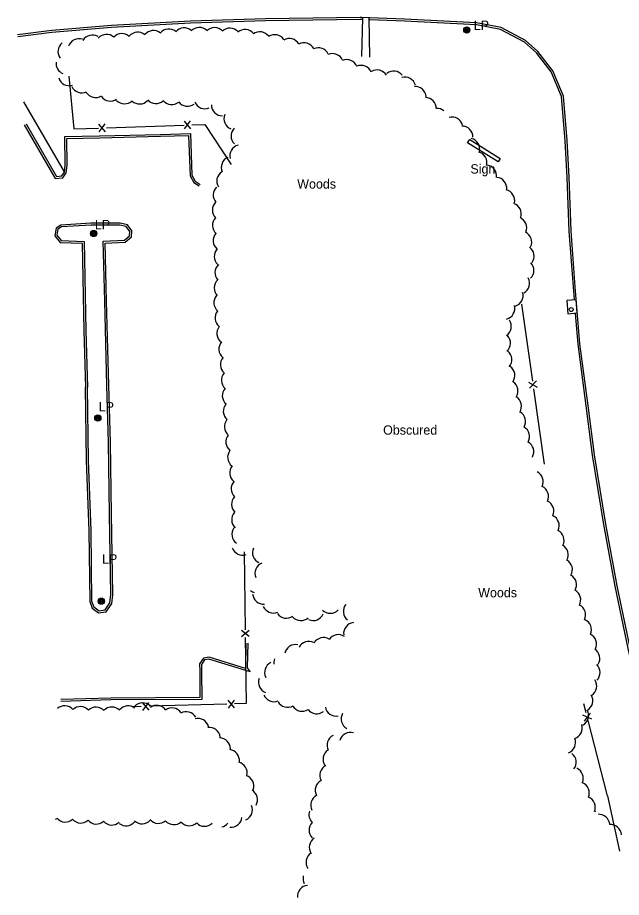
# Model space of a CAD drawing. Extents: x 2402803 to 2427059, y 6985292 to 6997652.
# Drawn here: x 2410127.8 to 2410438.3, y 6989147.3 to 6989599.8 of the extents above; entities that cross this region are included whole.
import ezdxf

# ---------------------------------------------------------------- set-up
doc = ezdxf.new("R2010")
doc.units = 0
for name, color, linetype in [('p_drainage conc drain', 7, 'Continuous'), ('p_dtm sidewalk', 7, 'Continuous'), ('p_road - paved curb', 7, 'Continuous'), ('p_road bridge end', 7, 'Continuous'), ('p_structure fence', 7, 'Continuous'), ('p_structure general', 7, 'Continuous'), ('p_structure sign', 7, 'Continuous'), ('p_utility manhole', 7, 'Continuous'), ('p_veg woods', 7, 'Continuous')]:
    doc.layers.add(name, color=color, linetype=linetype)

msp = doc.modelspace()

# ---------------------------------------------------------------- linework, layer by layer
at = {"layer": 'p_drainage conc drain'}
for points in [[(2410304.81, 6989579.78), (2410305.38, 6989599.73)], [(2410308.36, 6989599.64), (2410308.73, 6989579.44)]]:
    msp.add_lwpolyline(points, dxfattribs=at)
at = {"layer": 'p_dtm sidewalk'}
msp.add_lwpolyline([(2410151.87, 6989520.53), (2410130.92, 6989556.39)], dxfattribs=at)
at = {"layer": 'p_road - paved curb'}
for points in [[(2410304.81, 6989599.75), (2410304.03, 6989599.77), (2410255.34, 6989599.05), (2410216.69, 6989597.93), (2410176.02, 6989595.72), (2410145.35, 6989593.12), (2410127.76, 6989590.94)], [(2410308.42, 6989599.64), (2410304.81, 6989599.75)], [(2410460.84, 6989198.96), (2410452.78, 6989232.94), (2410442.78, 6989275.6), (2410436.11, 6989307.56), (2410430.27, 6989339.28), (2410424.46, 6989374.86), (2410421.18, 6989400.28), (2410417.04, 6989432.02), (2410414.64, 6989461.32), (2410412.46, 6989490.04), (2410411.44, 6989517.65), (2410410.5, 6989536.53), (2410408.53, 6989559.41), (2410403.06, 6989572.35), (2410395.37, 6989582.41), (2410389.01, 6989588.05), (2410376.52, 6989594.63), (2410363.85, 6989597.13), (2410326.82, 6989599), (2410308.9, 6989599.63), (2410308.42, 6989599.64)], [(2410304.78, 6989598.75), (2410304.02, 6989598.77), (2410255.36, 6989598.05), (2410216.73, 6989596.93), (2410176.09, 6989594.72), (2410145.45, 6989592.13), (2410127.88, 6989589.95)], [(2410414.16, 6989454.86), (2410413.64, 6989461.24), (2410411.46, 6989489.98), (2410410.44, 6989517.61), (2410409.5, 6989536.46), (2410407.55, 6989559.17), (2410402.19, 6989571.84), (2410394.63, 6989581.73), (2410388.44, 6989587.22), (2410376.18, 6989593.68), (2410363.73, 6989596.13), (2410326.78, 6989598), (2410308.87, 6989598.63), (2410308.4, 6989598.64)], [(2410132.09, 6989545.15), (2410147.71, 6989518.04), (2410150.53, 6989518.35), (2410151.85, 6989520.28), (2410152.21, 6989523.92), (2410152.06, 6989538.55), (2410169.85, 6989538.88), (2410201.3, 6989539.71), (2410216.64, 6989540.23), (2410217.46, 6989518.68), (2410219.11, 6989515.72), (2410221.66, 6989514.01)], [(2410131.22, 6989544.65), (2410147.17, 6989516.97), (2410151.1, 6989517.41), (2410152.82, 6989519.93), (2410153.21, 6989523.88), (2410153.07, 6989537.57), (2410169.87, 6989537.88), (2410201.33, 6989538.71), (2410215.68, 6989539.2), (2410216.47, 6989518.4), (2410218.35, 6989515.02), (2410221.1, 6989513.18)], [(2410174.7, 6989410.67), (2410173.57, 6989453.89), (2410172.78, 6989483.79), (2410183.13, 6989484.27), (2410186.37, 6989487), (2410186.44, 6989490.12), (2410184.23, 6989493.25), (2410180.5, 6989494.11), (2410165.49, 6989493.98), (2410149.94, 6989493.08), (2410147.57, 6989491.56), (2410146.87, 6989487.62), (2410149.62, 6989484.07), (2410160.99, 6989483.72), (2410161.84, 6989438.69), (2410162.73, 6989409.63)], [(2410173.7, 6989410.64), (2410172.57, 6989453.86), (2410171.75, 6989484.74), (2410182.74, 6989485.25), (2410185.38, 6989487.47), (2410185.43, 6989489.81), (2410183.63, 6989492.36), (2410180.39, 6989493.11), (2410165.52, 6989492.98), (2410150.26, 6989492.1), (2410148.48, 6989490.95), (2410147.93, 6989487.88), (2410150.12, 6989485.06), (2410161.97, 6989484.69), (2410162.84, 6989438.71), (2410163.73, 6989409.66)], [(2410459.87, 6989198.73), (2410451.81, 6989232.71), (2410441.8, 6989275.38), (2410435.13, 6989307.37), (2410429.28, 6989339.11), (2410423.47, 6989374.72), (2410420.19, 6989400.15), (2410416.05, 6989431.91), (2410414.76, 6989447.66)], [(2410162.47, 6989409.65), (2410163.04, 6989371.94), (2410164.35, 6989335.89), (2410164.86, 6989299.41), (2410166.19, 6989296.13), (2410169.42, 6989293.7), (2410173.33, 6989294.2), (2410176.16, 6989298.44), (2410176.8, 6989302.97), (2410176.12, 6989344.5), (2410175.5, 6989381.25), (2410174.7, 6989410.67)], [(2410163.47, 6989409.67), (2410164.04, 6989371.97), (2410165.35, 6989335.92), (2410165.86, 6989299.61), (2410167.01, 6989296.76), (2410169.7, 6989294.74), (2410172.75, 6989295.13), (2410175.2, 6989298.81), (2410175.8, 6989303.03), (2410175.12, 6989344.48), (2410174.5, 6989381.23), (2410173.7, 6989410.64)], [(2410245.11, 6989278), (2410244.92, 6989265.1), (2410244.94, 6989265.07), (2410226.26, 6989270.79), (2410223.38, 6989270.33), (2410221.29, 6989267.39), (2410221.42, 6989263.65), (2410221.48, 6989250.05), (2410175.64, 6989249.86), (2410149.99, 6989249.13)], [(2410246.11, 6989277.99), (2410245.92, 6989265.4), (2410247.33, 6989263.29), (2410226.19, 6989269.77), (2410223.95, 6989269.41), (2410222.3, 6989267.09), (2410222.42, 6989263.67), (2410222.48, 6989249.05), (2410175.66, 6989248.86), (2410150.02, 6989248.13)]]:
    msp.add_lwpolyline(points, dxfattribs=at)
at = {"layer": 'p_road bridge end'}
msp.add_lwpolyline([(2410415.64, 6989447.88), (2410415.08, 6989454.67), (2410410.22, 6989454.27), (2410410.78, 6989447.48)], close=True, dxfattribs=at)
at = {"layer": 'p_structure fence'}
for p, q in [((2410172.91, 6989541.08), (2410169.58, 6989544.97)), ((2410169.72, 6989540.97), (2410172.78, 6989545.08)), ((2410216.89, 6989542.6), (2410213.55, 6989546.49)), ((2410213.69, 6989542.49), (2410216.75, 6989546.6)), ((2410173.45, 6989543.07), (2410213.42, 6989544.45)), ((2410386.87, 6989452.35), (2410392.55, 6989412.8)), ((2410390.63, 6989412.32), (2410395.04, 6989409.72)), ((2410391.08, 6989409.15), (2410394.59, 6989412.89)), ((2410393.12, 6989408.84), (2410398.67, 6989370.15)), ((2410244.3, 6989324.95), (2410244.83, 6989284.96)), ((2410242.86, 6989284.73), (2410246.9, 6989281.59)), ((2410242.9, 6989281.53), (2410246.86, 6989284.79)), ((2410191.9, 6989247.47), (2410195.21, 6989243.55)), ((2410195.1, 6989247.55), (2410192.01, 6989243.47)), ((2410235.34, 6989246.69), (2410195.36, 6989245.59)), ((2410235.89, 6989248.67), (2410239.2, 6989244.76)), ((2410239.09, 6989248.76), (2410236, 6989244.67)), ((2410420.24, 6989242.17), (2410419.01, 6989246.95)), ((2410191.36, 6989245.48), (2410186.62, 6989245.35)), ((2410422.3, 6989242.09), (2410419.22, 6989237.99)), ((2410423.1, 6989238.99), (2410418.42, 6989241.09)), ((2410431.21, 6989199.59), (2410421.24, 6989238.3)), ((2410431.21, 6989199.59), (2410437.38, 6989171.09))]:
    msp.add_line(p, q, dxfattribs=at)
for points in [[(2410154.16, 6989569.57), (2410156.65, 6989542.49), (2410169.45, 6989542.93)], [(2410217.42, 6989544.59), (2410224.03, 6989544.82), (2410237.66, 6989524.24)], [(2410244.88, 6989280.96), (2410245.33, 6989246.96), (2410239.34, 6989246.8)]]:
    msp.add_lwpolyline(points, dxfattribs=at)
at = {"layer": 'p_structure general'}
msp.add_lwpolyline([(2410374.92, 6989525.54), (2410359.24, 6989535.42), (2410360.32, 6989537.14), (2410376, 6989527.26)], close=True, dxfattribs=at)
msp.add_circle((2410412.54, 6989449.63), 1, dxfattribs=at)
at = {"layer": 'p_utility manhole'}
for centre, radius in [((2410358.81, 6989593.42), 1.6), ((2410358.81, 6989593.42), 1.6), ((2410358.81, 6989593.42), 1.3), ((2410358.81, 6989593.42), 1.3), ((2410358.81, 6989593.42), 1), ((2410358.81, 6989593.42), 1), ((2410358.81, 6989593.42), 0.539), ((2410358.81, 6989593.42), 0.539), ((2410358.81, 6989593.42), 0.192), ((2410358.81, 6989593.42), 0.192), ((2410166.91, 6989488.73), 1.6), ((2410166.91, 6989488.73), 1.3), ((2410166.91, 6989488.73), 1), ((2410166.91, 6989488.73), 0.539), ((2410166.91, 6989488.73), 0.192), ((2410169.04, 6989393.83), 1.6), ((2410169.04, 6989393.83), 1.3), ((2410169.04, 6989393.83), 1), ((2410169.04, 6989393.83), 0.539), ((2410169.04, 6989393.83), 0.192), ((2410170.78, 6989299.66), 1.6), ((2410170.78, 6989299.66), 1.3), ((2410170.78, 6989299.66), 1), ((2410170.78, 6989299.66), 0.539), ((2410170.78, 6989299.66), 0.192)]:
    msp.add_circle(centre, radius, dxfattribs=at)
at = {"layer": 'p_veg woods'}
for centre, start, end in [((2410221.22, 6989589.04), 46.736, 136.736), ((2410166.26, 6989585.17), 59.4881, 149.4881), ((2410173.52, 6989585.52), 48.7796, 138.7796), ((2410181.44, 6989585.88), 47.8747, 137.8747), ((2410189.58, 6989586.62), 50.32, 140.32), ((2410197.58, 6989587.47), 50.9838, 140.9838), ((2410205.51, 6989588.26), 50.603, 140.603), ((2410213.38, 6989588.83), 49.1099, 139.1099), ((2410229.05, 6989588.95), 44.3168, 134.3168), ((2410236.97, 6989588.71), 43.2248, 133.2248), ((2410244.71, 6989587.98), 39.971, 129.971), ((2410252.37, 6989586.79), 36.3436, 126.3436), ((2410260.07, 6989585.3), 34.1784, 124.1784), ((2410154.18, 6989582.32), 128.0855, 218.0855), ((2410159.34, 6989583.28), 71.3453, 161.3453), ((2410267.57, 6989583.36), 30.4879, 120.4879), ((2410275.11, 6989581.14), 28.6076, 118.6076), ((2410282.47, 6989578.58), 25.6918, 115.6918), ((2410289.71, 6989575.62), 23.0818, 113.0818), ((2410153.19, 6989576.2), 173.0413, 246.8151), ((2410297.03, 6989572.53), 22.3454, 112.3454), ((2410304.51, 6989569.53), 23.3576, 113.3576), ((2410312.69, 6989567.19), 30.7669, 120.7669), ((2410321.21, 6989566.6), 38.1739, 128.1739), ((2410154.33, 6989570.38), 196.3936, 286.3936), ((2410326.91, 6989563.54), 15.6974, 105.6974), ((2410160.76, 6989566.71), 205.3136, 295.3136), ((2410332.24, 6989558.68), 3.9133, 93.9133), ((2410167.88, 6989564.29), 212.2202, 302.2202), ((2410175.45, 6989562.48), 215.2746, 305.2746), ((2410337.45, 6989553.05), 358.9718, 88.9718), ((2410182.75, 6989561.08), 223.7187, 313.7187), ((2410190.53, 6989561), 226.8481, 316.8481), ((2410198.87, 6989561.21), 222.0148, 312.0148), ((2410207.05, 6989560.71), 219.1474, 309.1474), ((2410215.17, 6989559.83), 216.8359, 306.8359), ((2410224.1, 6989558.5), 202.6173, 292.6173), ((2410233.12, 6989554.88), 179.7309, 269.7309), ((2410239.57, 6989547.83), 158.1394, 248.1394), ((2410343.49, 6989547.42), 51.9525, 92.6728), ((2410351.21, 6989542.96), 15.4092, 105.4092), ((2410243.19, 6989538.95), 136.4104, 226.4104), ((2410356.29, 6989538.34), 359.3948, 89.3948), ((2410359.81, 6989532.12), 346.3261, 76.3261), ((2410242.58, 6989528.7), 104.4021, 194.4021), ((2410238.2, 6989522.74), 114.1716, 204.1716), ((2410363.49, 6989525.22), 343.8284, 73.8284), ((2410368.52, 6989518.29), 351.7709, 81.7709), ((2410235.83, 6989515.67), 121.8309, 211.8309), ((2410373.71, 6989512), 353.9837, 83.9837), ((2410233.99, 6989508.58), 134.8033, 222.0412), ((2410377.8, 6989505.65), 347.4751, 77.4751), ((2410233.59, 6989500.81), 135.2191, 225.2191), ((2410381.18, 6989498.83), 341.8336, 71.8336), ((2410233.64, 6989492.97), 137.5072, 227.5072), ((2410384, 6989491.68), 337.2352, 67.2352), ((2410234.02, 6989485.04), 138.4255, 228.4255), ((2410386.56, 6989484.32), 334.2401, 64.2401), ((2410387.82, 6989477.04), 325.188, 55.188), ((2410234.55, 6989476.97), 137.1151, 227.1151), ((2410234.92, 6989468.65), 132.6198, 222.6198), ((2410387.71, 6989469.81), 313.7924, 43.7924), ((2410234.53, 6989460.75), 133.8634, 223.8634), ((2410385.46, 6989463.17), 298.5635, 28.5635), ((2410234.37, 6989453.13), 139.2274, 229.2274), ((2410382.12, 6989456.84), 286.3838, 16.3838), ((2410377.86, 6989450.21), 284.7522, 14.7522), ((2410234.99, 6989445.32), 141.5952, 231.5952), ((2410235.92, 6989437.4), 141.9446, 231.9446), ((2410376.02, 6989440.99), 303.9523, 33.9523), ((2410236.95, 6989429.34), 140.1421, 230.1421), ((2410375.64, 6989432.39), 312.5949, 42.5949), ((2410376.33, 6989423.9), 320.1038, 50.1038), ((2410237.69, 6989421.28), 138.8152, 228.8152), ((2410377.89, 6989415.68), 325.3573, 55.3573), ((2410238.22, 6989413.29), 138.5675, 228.5675), ((2410379.47, 6989407.77), 326.5584, 56.5584), ((2410238.71, 6989405.32), 138.7411, 228.7411), ((2410381.28, 6989399.89), 327.9678, 57.9678), ((2410239.22, 6989397.36), 139.1169, 229.1169), ((2410383.39, 6989392.06), 329.717, 59.717), ((2410239.77, 6989389.46), 140.2103, 230.2103), ((2410385.45, 6989384.32), 329.9538, 59.9538), ((2410240.52, 6989381.59), 141.5392, 231.5392), ((2410387.62, 6989376.57), 330.7326, 60.7326), ((2410241.45, 6989373.68), 141.9259, 231.9259), ((2410389.88, 6989368.86), 60.6601, 61.2729), ((2410242.47, 6989365.66), 140.5645, 230.5645), ((2410392.48, 6989361.12), 333.6646, 63.6646), ((2410243.25, 6989357.42), 136.5369, 226.5369), ((2410395.21, 6989353.5), 335.0588, 65.0588), ((2410243.45, 6989349.4), 135.7783, 225.7783), ((2410397.98, 6989345.98), 335.2605, 65.2605), ((2410243.52, 6989341.54), 137.4128, 227.4128), ((2410400.68, 6989338.5), 334.7084, 64.7084), ((2410243.64, 6989334.01), 144.3701, 234.3701), ((2410403.2, 6989331), 333.4659, 63.4659), ((2410405.4, 6989323.47), 331.2602, 61.2602), ((2410243.52, 6989328.96), 199.1669, 289.1669), ((2410254.22, 6989324.61), 155.4515, 245.4515), ((2410255.49, 6989314), 112.6913, 202.6913), ((2410407.49, 6989315.82), 330.1806, 60.1806), ((2410409.58, 6989308.1), 330.1806, 60.1806), ((2410250.89, 6989309.67), 234.5939, 256.0857), ((2410411.77, 6989300.35), 330.8885, 60.8885), ((2410254.28, 6989303.79), 184.8021, 274.8021), ((2410259.31, 6989299.21), 203.4466, 293.4466), ((2410300.97, 6989294.36), 140.6412, 230.6412), ((2410414.31, 6989292.58), 333.4963, 63.4963), ((2410265.96, 6989296.58), 215.8909, 305.8909), ((2410273.44, 6989295.36), 221.9601, 311.9601), ((2410279.74, 6989295.34), 246.4117, 336.4117), ((2410288.58, 6989299.11), 225.429, 315.429), ((2410301.11, 6989283.01), 96.2303, 186.2303), ((2410417.31, 6989284.97), 336.0203, 66.0203), ((2410292.68, 6989276.82), 55.6725, 145.6725), ((2410419.92, 6989277.57), 333.8958, 63.8958), ((2410277.57, 6989273.35), 62.6721, 152.6721), ((2410285.13, 6989275.31), 59.9113, 149.9113), ((2410270.73, 6989271.71), 78.2031, 168.2031), ((2410421.65, 6989270.17), 328.0827, 58.0827), ((2410265.16, 6989267.89), 157.6882, 186.4453), ((2410260.46, 6989262.98), 116.2716, 206.2716), ((2410421.72, 6989263), 315.7846, 45.7846), ((2410257.3, 6989257.95), 159.411, 249.411), ((2410420, 6989256.02), 303.5208, 33.5208), ((2410259.68, 6989253.56), 202.4481, 292.4481), ((2410417.96, 6989248.51), 300.4035, 30.4035), ((2410192.06, 6989241.68), 46.5204, 136.5204), ((2410266.64, 6989250.76), 209.5518, 299.5518), ((2410152.01, 6989240.21), 42.1249, 132.1249), ((2410160, 6989239.81), 42.1249, 132.1249), ((2410168.06, 6989239.51), 43.0252, 133.0252), ((2410176.19, 6989239.58), 44.7979, 134.7979), ((2410184.62, 6989240.18), 51.4694, 141.4694), ((2410199.35, 6989240.45), 37.2004, 127.2004), ((2410207.11, 6989239.09), 35.4876, 125.4876), ((2410214.46, 6989237.17), 29.7144, 119.7144), ((2410274.18, 6989248.67), 211.9716, 301.9716), ((2410281.64, 6989247.41), 217.7011, 307.7011), ((2410291.63, 6989246.23), 190.7137, 280.7137), ((2410299.86, 6989239.11), 150.4933, 240.4933), ((2410415.78, 6989240.9), 299.3304, 29.3304), ((2410220.51, 6989233.68), 14.6909, 104.6909), ((2410226.39, 6989229.06), 7.227, 97.227), ((2410412.59, 6989234.46), 287.7554, 17.7554), ((2410231.64, 6989223.71), 0.103, 90.103), ((2410292.57, 6989225.59), 117.0413, 207.0413), ((2410298.95, 6989226.53), 74.2537, 164.2537), ((2410409.12, 6989226.96), 291.6898, 21.6898), ((2410236.21, 6989217.74), 353.142, 83.142), ((2410290.54, 6989218.33), 123.5773, 213.5773), ((2410409.46, 6989216.83), 322.3957, 52.3957), ((2410240.22, 6989211.31), 347.1765, 77.1765), ((2410288.88, 6989210.1), 117.8851, 207.8851), ((2410413.08, 6989208.57), 335.7258, 65.7258), ((2410243.65, 6989204.55), 341.1572, 71.1572), ((2410286.52, 6989202.45), 117.8851, 207.8851), ((2410416.16, 6989201.06), 337.3944, 67.3944), ((2410245.53, 6989197.55), 330.043, 60.043), ((2410284.17, 6989194.81), 117.8851, 207.8851), ((2410419.25, 6989193.69), 337.6457, 67.6457), ((2410242.94, 6989192.43), 293.0672, 23.0672), ((2410144.35, 6989192.22), 300.5795, 311.3481), ((2410152.33, 6989191.72), 221.3481, 311.3481), ((2410160.3, 6989191.21), 221.3481, 311.3481), ((2410237.56, 6989189.05), 264.0845, 354.0845), ((2410283.26, 6989189.92), 161.486, 225.3477), ((2410422.2, 6989186.44), 58.7883, 67.2692), ((2410426.68, 6989184.42), 3.8028, 93.8028), ((2410168.28, 6989190.7), 221.3481, 311.3481), ((2410176.25, 6989190.19), 221.3481, 311.3481), ((2410183.57, 6989189.78), 231.031, 321.031), ((2410191.76, 6989190.81), 227.5361, 317.5361), ((2410200.2, 6989191.02), 221.187, 311.187), ((2410208.18, 6989190.42), 221.0616, 311.0616), ((2410216.05, 6989189.84), 222.7655, 312.7655), ((2410223.95, 6989189.53), 224.0392, 314.0392), ((2410231.48, 6989189.07), 283.2554, 321.1285), ((2410283.31, 6989181.92), 135.3477, 225.3477), ((2410432.69, 6989179.15), 3.8028, 93.8028), ((2410283.46, 6989173.09), 123.3866, 213.3866), ((2410281.76, 6989165.37), 123.8811, 213.8811), ((2410280.22, 6989157.11), 167.1447, 208.2928), ((2410277.37, 6989147.89), 95.8171, 185.8171)]:
    msp.add_arc(centre, 5.65, start, end, dxfattribs=at)

# ---------------------------------------------------------------- texts
at = {"layer": 'p_structure sign'}
msp.add_text('Sign', height=4.8, dxfattribs=at).set_placement((2410360.67, 6989519.56))
at = {"layer": 'p_utility manhole'}
for p in [(2410358.81, 6989593.42), (2410358.81, 6989593.42), (2410163.94, 6989490.95), (2410165.93, 6989397.25), (2410167.62, 6989318.99)]:
    msp.add_text('  LP', height=4.8, dxfattribs=at).set_placement(p)
at = {"layer": 'p_veg woods'}
for s, p in [('Woods', (2410271.59, 6989511.83)), ('Obscured', (2410315.78, 6989385.29)), ('Woods', (2410364.68, 6989301.65))]:
    msp.add_text(s, height=4.8, dxfattribs=at).set_placement(p)

doc.saveas('drawing.dxf')
